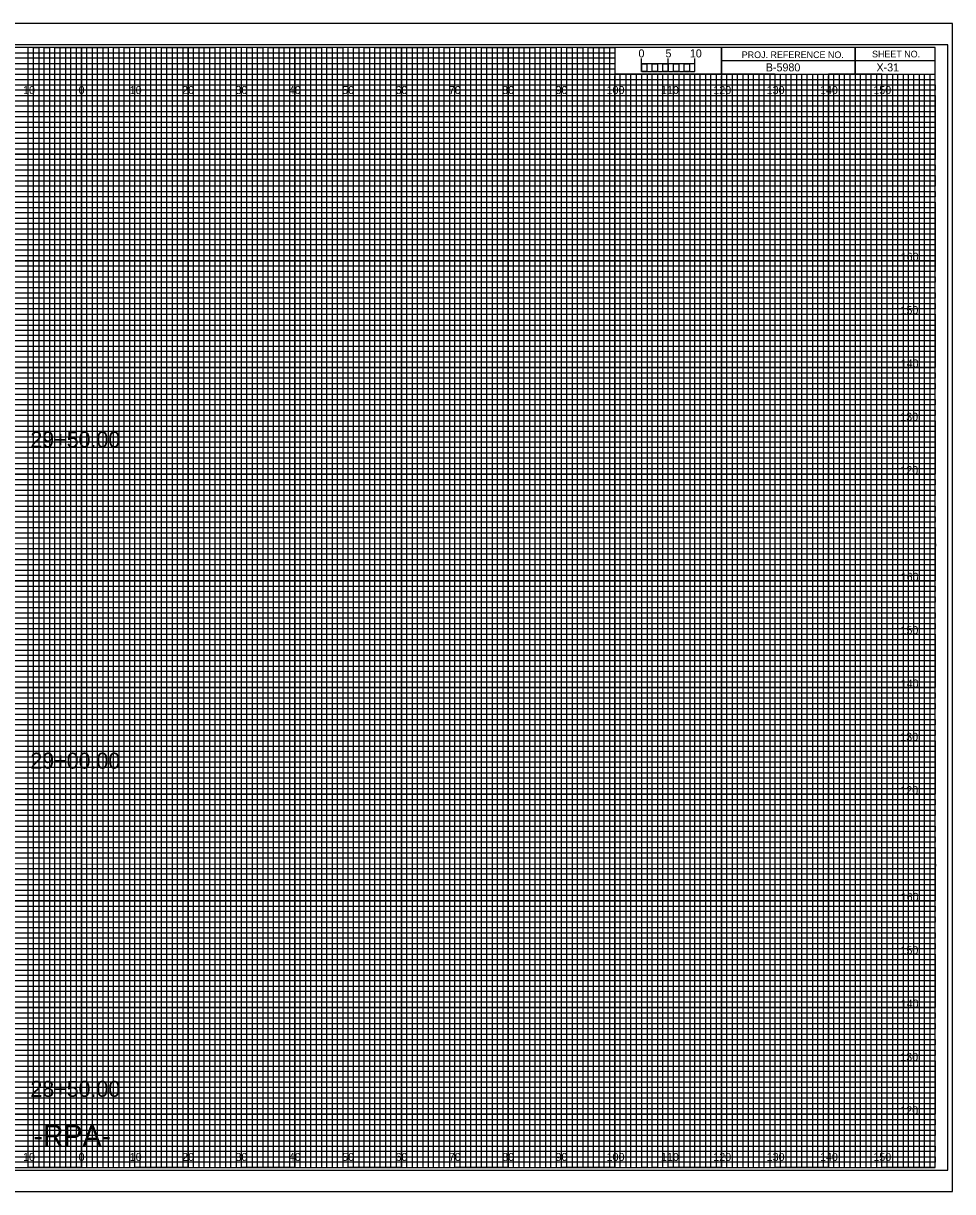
# Model space of a CAD drawing. Extents: x -13 to 323, y -5 to 1974.
# Drawn here: x 149.1 to 323.3, y 1535.5 to 1754.5 of the extents above; entities that cross this region are included whole.
import ezdxf

# ---------------------------------------------------------------- set-up
doc = ezdxf.new("R2010")
doc.units = 0
for name, color, linetype in [('Exist Cross Section Cell', 7, 'Continuous'), ('Exist XS Center Line Elevation Label', 7, 'Continuous'), ('Exist XS Ground Line', 7, 'Continuous'), ('Prop CMT Bridge Girder Bottom Critical Point Inside', 7, 'Continuous'), ('Prop CMT Guardrail Graphics', 7, 'Continuous'), ('Prop CMT Guardrail Widen Shoulder', 7, 'Continuous'), ('Prop CMT Pvmt Course 1', 7, 'Continuous'), ('Prop CMT Pvmt Course 2', 7, 'Continuous'), ('Prop CMT Pvmt Course 3', 7, 'Continuous'), ('Prop CMT Pvmt Surface', 7, 'Continuous'), ('Prop CMT Pvmt Surface Shoulder', 7, 'Continuous'), ('Prop CMT Shld Paved Course 1', 7, 'Continuous'), ('Prop CMT Shld Paved Course 2', 7, 'Continuous'), ('Prop CMT Shld Paved Course 3', 7, 'Continuous'), ('Prop CMT Slope Grass', 7, 'Continuous'), ('Prop CMT Subgrade Earthwork', 7, 'Continuous'), ('Scratch_Level_1', 7, 'Continuous')]:
    doc.layers.add(name, color=color, linetype=linetype)

msp = doc.modelspace()

# ---------------------------------------------------------------- linework, layer by layer
at = {"layer": 'Exist XS Center Line Elevation Label'}
for points in [[(145, 1540), (155, 1540), (155, 1750), (165, 1750), (165, 1540), (175, 1540), (175, 1750), (185, 1750), (185, 1540), (195, 1540), (195, 1750), (205, 1750), (205, 1540), (215, 1540), (215, 1750), (225, 1750), (225, 1540), (235, 1540), (235, 1750), (245, 1750), (245, 1540), (255, 1540), (255, 1750), (259.93, 1750), (260, 1750), (260, 1745), (264.99, 1745), (264.99, 1540), (275, 1540), (275, 1745), (285, 1745), (285, 1540), (295, 1540), (295, 1745), (305, 1745), (305, 1540), (315, 1540), (315, 1745)], [(0, 1745), (275, 1745)], [(0, 1725), (320, 1725), (320, 1735), (0, 1735)], [(0, 1705), (320, 1705), (320, 1715), (0, 1715)], [(0, 1685), (320, 1685), (320, 1695), (0, 1695)], [(0, 1665), (320, 1665), (320, 1675), (0, 1675)], [(0, 1645), (320, 1645), (320, 1655), (0, 1655)], [(0, 1625), (320, 1625), (320, 1635), (0, 1635)], [(0, 1605), (320, 1605), (320, 1615), (0, 1615)], [(0, 1585), (320, 1585), (320, 1595), (0, 1595)], [(0, 1565), (320, 1565), (320, 1575), (0, 1575)], [(0, 1545), (320, 1545), (320, 1555), (0, 1555)]]:
    msp.add_lwpolyline(points, dxfattribs=at)
at = {"layer": 'Exist XS Ground Line'}
for p, q in [((150, 1750), (140, 1750)), ((150, 1540), (150, 1750)), ((170, 1750), (160, 1750)), ((160, 1750), (160, 1540)), ((170, 1540), (170, 1750)), ((190, 1750), (180, 1750)), ((180, 1750), (180, 1540)), ((190, 1540), (190, 1750)), ((210, 1750), (200, 1750)), ((200, 1750), (200, 1540)), ((210, 1540), (210, 1750)), ((230, 1750), (220, 1750)), ((220, 1750), (220, 1540)), ((230, 1540), (230, 1750)), ((250, 1750), (240, 1750)), ((240, 1750), (240, 1540)), ((250, 1540), (250, 1750)), ((260, 1750), (260, 1540)), ((270, 1540), (270, 1745)), ((290, 1745), (280, 1745)), ((280, 1745), (280, 1540)), ((290, 1540), (290, 1745)), ((310, 1745), (300, 1745)), ((300, 1745), (300, 1540)), ((310, 1540), (310, 1745)), ((160, 1540), (150, 1540)), ((180, 1540), (170, 1540)), ((200, 1540), (190, 1540)), ((220, 1540), (210, 1540)), ((240, 1540), (230, 1540)), ((260, 1540), (250, 1540)), ((280, 1540), (270, 1540)), ((300, 1540), (290, 1540)), ((320, 1540), (310, 1540)), ((320, 1540), (320, 1540))]:
    msp.add_line(p, q, dxfattribs=at)
for points in [[(0, 1740), (320, 1740), (320, 1730), (0, 1730)], [(0, 1720), (320, 1720), (320, 1710), (0, 1710)], [(0, 1700), (320, 1700), (320, 1690), (0, 1690)], [(0, 1680), (320, 1680), (320, 1670), (0, 1670)], [(0, 1660), (320, 1660), (320, 1650), (0, 1650)], [(0, 1640), (320, 1640), (320, 1630), (0, 1630)], [(0, 1620), (320, 1620), (320, 1610), (0, 1610)], [(0, 1600), (320, 1600), (320, 1590), (0, 1590)], [(0, 1580), (320, 1580), (320, 1570), (0, 1570)], [(0, 1560), (320, 1560), (320, 1550), (0, 1550)]]:
    msp.add_lwpolyline(points, dxfattribs=at)
at = {"layer": 'Prop CMT Pvmt Course 2'}
for p, q in [((265, 1745.49), (265, 1747.9)), ((265, 1746.9), (265, 1747.9)), ((270, 1745.49), (270, 1747.9)), ((275, 1745.49), (275, 1747.9)), ((275, 1746.9), (275, 1747.9))]:
    msp.add_line(p, q, dxfattribs=at)
for points in [[(275, 1746.9), (265, 1746.9), (265, 1745.49), (275, 1745.49)], [(265, 1746.9), (266, 1746.9), (266, 1745.49), (265, 1745.49)], [(267, 1746.9), (268, 1746.9), (268, 1745.49), (267, 1745.49)], [(269, 1746.9), (270, 1746.9), (270, 1745.49), (269, 1745.49)], [(271, 1746.9), (272, 1746.9), (272, 1745.49), (271, 1745.49)], [(273, 1746.9), (274, 1746.9), (274, 1745.49), (273, 1745.49)]]:
    msp.add_lwpolyline(points, close=True, dxfattribs=at)
at = {"layer": 'Prop CMT Pvmt Course 3'}
msp.add_lwpolyline([(-13.4, 1535.5), (323.3, 1535.5), (323.3, 1754.5), (-13.4, 1754.5)], close=True, dxfattribs=at)
at = {"layer": 'Prop CMT Pvmt Surface'}
for p, q in [((150, 1540), (150, 1750)), ((160, 1540), (160, 1750)), ((170, 1540), (170, 1750)), ((180, 1540), (180, 1750)), ((190, 1540), (190, 1750)), ((200, 1540), (200, 1750)), ((210, 1540), (210, 1750)), ((220, 1540), (220, 1750)), ((230, 1540), (230, 1750)), ((240, 1540), (240, 1750)), ((250, 1540), (250, 1750)), ((260, 1540), (260, 1744.69)), ((270, 1540), (270, 1744.69)), ((280, 1540), (280, 1744.69)), ((290, 1540), (290, 1744.69)), ((300, 1540), (300, 1744.69)), ((310, 1540), (310, 1744.69)), ((0, 1740), (320, 1740)), ((0, 1730), (320, 1730)), ((0, 1720), (320, 1720)), ((0, 1710), (320, 1710)), ((0, 1700), (320, 1700)), ((0, 1690), (320, 1690)), ((0, 1680), (320, 1680)), ((0, 1670), (320, 1670)), ((0, 1660), (320, 1660)), ((0, 1650), (320, 1650)), ((0, 1640), (320, 1640)), ((0, 1630), (320, 1630)), ((0, 1620), (320, 1620)), ((0, 1610), (320, 1610)), ((0, 1600), (320, 1600)), ((0, 1590), (320, 1590)), ((0, 1580), (320, 1580)), ((0, 1570), (320, 1570)), ((0, 1560), (320, 1560)), ((0, 1550), (320, 1550))]:
    msp.add_line(p, q, dxfattribs=at)
at = {"layer": 'Prop CMT Pvmt Surface Shoulder'}
for p, q in [((323.3, 1754.5), (-13.4, 1754.5)), ((-13.4, 1535.5), (323.3, 1535.5))]:
    msp.add_line(p, q, dxfattribs=at)
at = {"layer": 'Prop CMT Shld Paved Course 1'}
for p, q in [((0, 1749), (260, 1749)), ((260, 1747.98), (0, 1747.98)), ((260, 1749), (260, 1747.98)), ((0, 1747), (260, 1747)), ((260, 1745.89), (0, 1745.89)), ((260, 1747), (260, 1745.89)), ((0, 1744), (320, 1744))]:
    msp.add_line(p, q, dxfattribs=at)
for points in [[(0, 1743), (270, 1743), (320, 1743), (320, 1742), (0, 1742)], [(0, 1741), (320, 1741), (320, 1739), (0, 1739)], [(0, 1738), (320, 1738), (320, 1737), (0, 1736.98)], [(0, 1736), (320, 1736), (320, 1734), (0, 1734)], [(0, 1733), (320, 1733), (320, 1732), (0, 1732)], [(0, 1731), (320, 1731), (320, 1729), (0, 1729)], [(0, 1728), (320, 1728), (320, 1727), (0, 1727)], [(0, 1726), (320, 1726), (320, 1724), (0, 1724)], [(0, 1723), (320, 1723), (320, 1722), (0, 1722)], [(0, 1721), (320, 1721), (320, 1719), (0, 1719)], [(0, 1718), (320, 1718), (320, 1717), (0, 1717)], [(0, 1716), (320, 1716), (320, 1713.95), (320, 1713), (320, 1712), (0, 1712)], [(0, 1714), (320, 1714), (320, 1713), (0, 1713)], [(0, 1711), (320, 1711), (320, 1709), (0, 1709.03)], [(0, 1709.03), (320, 1709), (320, 1708), (0, 1708)], [(0, 1707), (320, 1707), (320, 1706), (0, 1706)], [(0, 1704), (320, 1704), (320, 1703), (0, 1703)], [(0, 1702), (320, 1702), (320, 1701), (0, 1701)], [(-0.07, 1698.89), (320, 1698.89), (320, 1697.88), (-0.07, 1697.88)], [(0, 1697), (320, 1697), (320, 1696), (0, 1696)], [(0, 1694), (320, 1694), (320, 1693), (0, 1693)], [(0, 1692), (320, 1692), (320, 1691), (0, 1691)], [(0, 1689), (320, 1689), (320, 1688), (0, 1688)], [(0, 1687), (320, 1687), (320, 1686), (0, 1686)], [(0, 1684), (320, 1684), (320, 1683), (0, 1683)], [(0, 1682), (320, 1682), (320, 1681), (0, 1681)], [(0, 1679), (320, 1679), (319.99, 1677.98), (0, 1678)], [(0, 1677), (320, 1677), (320, 1676), (0, 1676)], [(0, 1674), (320, 1674), (320, 1673), (0, 1673)], [(0, 1672), (320, 1672), (320, 1671), (0, 1671)], [(0, 1669), (320, 1669), (320, 1668), (0, 1668)], [(0, 1667), (320, 1667), (320, 1666), (0, 1666)], [(0, 1664), (320, 1664), (320, 1663), (0, 1663)], [(0, 1662), (320, 1662), (320, 1661), (0, 1661)], [(0, 1659), (320, 1659), (320, 1658), (0, 1658)], [(0, 1656.99), (320.07, 1656.91), (320, 1656), (0, 1656)], [(0, 1654), (320, 1654), (320, 1653), (0, 1653)], [(0, 1652), (320, 1652), (320, 1651), (0, 1651)], [(0, 1649), (320, 1649), (320, 1648), (0, 1648)], [(0, 1647), (320, 1647), (320, 1646), (0, 1646)], [(0, 1644), (320, 1644), (320, 1643), (0, 1643)], [(0, 1642), (320, 1642), (320, 1641), (0, 1641)], [(0, 1639), (320, 1639), (320, 1638), (0, 1638)], [(0, 1637), (320, 1637), (320, 1636), (0, 1636)], [(0, 1634), (320, 1634), (320, 1633), (0, 1633)], [(0, 1632), (320, 1632), (320, 1631), (0, 1631)], [(0, 1629), (320, 1629), (320, 1628), (0, 1628)], [(0, 1627), (320, 1627), (320, 1626), (0, 1626)], [(0, 1624), (320, 1624), (320, 1623), (0, 1623)], [(0, 1622), (320, 1622), (320, 1621), (0, 1621)], [(0, 1619), (320, 1619), (319.99, 1617.98), (0, 1618)], [(0, 1617), (320, 1617), (320, 1616), (0, 1616)], [(0, 1614), (320, 1614), (320, 1613), (0, 1613)], [(0, 1612), (320, 1612), (320, 1611), (0, 1611)], [(0, 1609), (320, 1609), (320, 1608), (0, 1608)], [(0, 1607), (320, 1607), (320, 1606), (0, 1606)], [(0, 1604), (320, 1604), (320, 1603), (0, 1603)], [(0, 1602), (320, 1602), (320, 1601), (0, 1601)], [(0, 1599), (320, 1599), (320, 1598), (0, 1598)], [(0, 1596.99), (320.07, 1596.91), (320, 1596), (0, 1596)], [(0, 1594), (320, 1594), (320, 1593), (0, 1593)], [(0, 1592), (320, 1592), (320, 1591), (0, 1591)], [(0, 1589), (320, 1589), (320, 1588), (0, 1588)], [(0, 1587), (320, 1587), (320, 1586), (0, 1586)], [(0, 1584), (320, 1584), (320, 1583), (0, 1583)], [(0, 1582), (320, 1582), (320, 1581), (0, 1581)], [(0, 1579), (320, 1579), (320, 1578), (0, 1578)], [(0, 1577), (320, 1577), (320, 1576), (0, 1576)], [(0, 1574), (320, 1574), (320, 1573), (0, 1573)], [(0, 1572), (320, 1572), (320, 1571), (0, 1571)], [(0, 1569), (320, 1569), (320, 1568), (0, 1568)], [(0, 1567), (320, 1567), (320, 1566), (0, 1566)], [(0, 1564), (320, 1564), (320, 1563), (0, 1563)], [(0, 1562), (320, 1562), (320, 1561), (0, 1561)], [(0, 1559), (320, 1559), (320, 1558), (0, 1558)], [(0, 1557), (320, 1557), (320, 1556), (0, 1556)], [(0, 1554), (320, 1554), (320, 1553), (0, 1553)], [(0, 1552), (320, 1552), (320, 1551), (0, 1551)], [(0, 1549), (320, 1549), (320, 1548), (0, 1548)], [(0, 1547), (320, 1547), (320, 1546), (0, 1546)], [(0, 1544), (320, 1544), (320, 1543), (0, 1543)], [(0, 1542), (320, 1542), (320, 1541), (0, 1541)]]:
    msp.add_lwpolyline(points, dxfattribs=at)
at = {"layer": 'Prop CMT Shld Paved Course 2'}
for p, q in [((305, 1750), (305, 1745)), ((305, 1745), (305, 1750)), ((280, 1747.5), (280, 1745)), ((320, 1747.49), (280, 1747.49)), ((280, 1745), (320, 1745))]:
    msp.add_line(p, q, dxfattribs=at)
for points in [[(320, 1750), (0, 1750), (0, 1540), (320, 1540)], [(280, 1750), (260, 1750), (260, 1745.03), (280, 1745.03)], [(320, 1750), (280, 1750), (280, 1745), (320, 1745)]]:
    msp.add_lwpolyline(points, close=True, dxfattribs=at)
at = {"layer": 'Prop CMT Shld Paved Course 3'}
for p, q in [((267, 1745), (266.01, 1745)), ((266.01, 1745), (266.01, 1540)), ((267, 1540), (267, 1745)), ((269, 1745), (268, 1745)), ((268, 1745), (268, 1540)), ((269, 1540), (269, 1745)), ((266.01, 1540), (265, 1540)), ((268, 1540), (267, 1540))]:
    msp.add_line(p, q, dxfattribs=at)
for points in [[(150, 1540), (151, 1540), (151, 1750), (152, 1750), (152, 1540)], [(152, 1540), (153, 1540), (153, 1750), (154, 1750), (154, 1540)], [(155, 1540), (156, 1540), (156, 1750), (157, 1750), (157, 1540)], [(157, 1540), (158, 1540), (158, 1750), (159, 1750), (159, 1540)], [(160, 1540), (161, 1540), (161, 1750), (162, 1750), (162, 1540)], [(162, 1540), (163, 1540), (163, 1750), (164, 1750), (164, 1540)], [(165, 1540), (166, 1540), (166, 1750), (167, 1750), (167, 1540)], [(167, 1540), (168, 1540), (168, 1750), (169, 1750), (169, 1540)], [(170, 1540), (171, 1540), (171, 1750), (172, 1750), (172, 1540)], [(172, 1540), (173, 1540), (173, 1750), (174, 1750), (174, 1540)], [(175, 1540), (176, 1540), (176, 1750), (177, 1750), (177, 1540)], [(177, 1540), (178, 1540), (178, 1750), (179, 1750), (179, 1540)], [(180, 1540), (181, 1540), (181, 1750), (182, 1750), (182, 1540)], [(182, 1540), (183, 1540), (183, 1750), (184, 1750), (184, 1540)], [(185, 1540), (186, 1540), (186, 1750), (187, 1750), (187, 1540)], [(187, 1540), (188, 1540), (188, 1750), (189, 1750), (189, 1540)], [(190, 1540), (191, 1540), (191, 1750), (192, 1750), (192, 1540)], [(192, 1540), (193, 1540), (193, 1750), (194, 1750), (194, 1540)], [(195, 1540), (196, 1540), (196, 1750), (197, 1750), (197, 1540)], [(197, 1540), (198, 1540), (198, 1750), (199, 1750), (199, 1540)], [(200, 1540), (201, 1540), (201, 1750), (202, 1750), (202, 1540)], [(202, 1540), (203, 1540), (203, 1750), (204, 1750), (204, 1540)], [(205, 1540), (206, 1540), (206, 1750), (207, 1750), (207, 1540)], [(207, 1540), (208, 1540), (208, 1750), (209, 1750), (209, 1540)], [(210, 1540), (211, 1540), (211, 1750), (212, 1750), (212, 1540)], [(212, 1540), (213, 1540), (213, 1750), (214, 1750), (214, 1540)], [(215, 1540), (216, 1540), (216, 1750), (217, 1750), (217, 1540)], [(217, 1540), (218, 1540), (218, 1750), (219, 1750), (219, 1540)], [(220, 1540), (221, 1540), (221, 1750), (222, 1750), (222, 1540)], [(222, 1540), (223, 1540), (223, 1750), (224, 1750), (224, 1540)], [(225, 1540), (226, 1540), (226, 1750), (227, 1750), (227, 1540)], [(227, 1540), (228, 1540), (228, 1750), (229, 1750), (229, 1540)], [(230, 1540), (231, 1540), (231, 1750), (232, 1750), (232, 1540)], [(232, 1540), (233, 1540), (233, 1750), (234, 1750), (234, 1540)], [(235, 1540), (236, 1540), (236, 1750), (237, 1750), (237, 1540)], [(237, 1540), (238, 1540), (238, 1750), (239, 1750), (239, 1540)], [(240, 1540), (241, 1540), (241, 1750), (242, 1750), (242, 1540)], [(242, 1540), (243, 1540), (243, 1750), (244, 1750), (244, 1540)], [(245, 1540), (246, 1540), (246, 1750), (247, 1750), (247, 1540)], [(247, 1540), (248, 1540), (248, 1750), (249, 1750), (249, 1540)], [(250, 1540), (251, 1540), (251, 1750), (252, 1750), (252, 1540)], [(252, 1540), (253, 1540), (253, 1750), (254, 1750), (254, 1540)], [(255, 1540), (256, 1540), (256, 1750), (257, 1750), (257, 1540)], [(257, 1540), (258, 1540), (258, 1750), (259, 1750), (259, 1540)], [(260, 1540), (261, 1540), (261, 1745), (262.02, 1745), (262.02, 1540)], [(262, 1540), (263, 1540), (263, 1745), (263.99, 1745), (263.99, 1540)], [(270, 1540), (270.98, 1540), (270.98, 1745), (272, 1745), (272, 1540)], [(272, 1540), (273, 1540), (273, 1745), (274.05, 1745), (274.05, 1540)], [(275, 1540), (276, 1540), (276, 1745), (277, 1745), (277, 1540)], [(277, 1540), (278, 1540), (278, 1745), (279, 1745), (279, 1540)], [(280, 1540), (281, 1540), (281, 1745), (282, 1745), (282, 1540)], [(282, 1540), (283, 1540), (283, 1745), (284, 1745), (284, 1540)], [(285, 1540), (286, 1540), (286, 1745), (287, 1745), (287, 1540)], [(287, 1540), (288, 1540), (288, 1745), (289, 1745), (289, 1540)], [(290, 1540), (291, 1540), (291, 1745), (292, 1745), (292, 1540)], [(292, 1540), (293, 1540), (293, 1745), (294, 1745), (294, 1540)], [(295, 1540), (296, 1540), (296, 1745), (297, 1745), (297, 1540)], [(297, 1540), (298, 1540), (298, 1745), (299, 1745), (299, 1540)], [(300, 1540), (301, 1540), (301, 1745), (302, 1745), (302, 1540)], [(302, 1540), (303, 1540), (303, 1745), (304, 1745), (304, 1540)], [(305, 1540), (306, 1540), (306, 1745), (307, 1745), (307, 1540)], [(307, 1540), (308, 1540), (308, 1745), (309, 1745), (309, 1540)], [(310, 1540), (311, 1540), (311, 1745), (312, 1745), (312, 1540)], [(312, 1540), (313, 1540), (313, 1745), (314, 1745), (314, 1540)], [(315, 1540), (316, 1540), (316, 1745), (317, 1745), (317, 1540)], [(317, 1540), (318, 1540), (318, 1745), (319, 1745), (319, 1540)]]:
    msp.add_lwpolyline(points, dxfattribs=at)
at = {"layer": 'Prop CMT Subgrade Earthwork'}
msp.add_lwpolyline([(-10.8, 1539.5), (322.4, 1539.5), (322.4, 1750.5), (-10.8, 1750.5)], close=True, dxfattribs=at)

# ---------------------------------------------------------------- texts
at = {"layer": 'Exist Cross Section Cell'}
for s, p in [('10', (149.04, 1741.25)), ('0', (159.45, 1741.25)), ('0', (159.45, 1741.25)), ('10', (169.04, 1741.25)), ('20', (178.86, 1741.25)), ('30', (188.86, 1741.25)), ('40', (198.86, 1741.25)), ('50', (208.86, 1741.25)), ('60', (218.86, 1741.25)), ('70', (228.86, 1741.25)), ('80', (238.86, 1741.25)), ('90', (248.86, 1741.25)), ('100', (258.44, 1741.25)), ('110', (268.62, 1741.25)), ('120', (278.44, 1741.25)), ('130', (288.44, 1741.25)), ('140', (298.44, 1741.25)), ('150', (308.44, 1741.25)), ('10', (149.04, 1541.25)), ('0', (159.45, 1541.25)), ('0', (159.45, 1541.25)), ('10', (169.04, 1541.25)), ('20', (178.86, 1541.25)), ('30', (188.86, 1541.25)), ('40', (198.86, 1541.25)), ('50', (208.86, 1541.25)), ('60', (218.86, 1541.25)), ('70', (228.86, 1541.25)), ('80', (238.86, 1541.25)), ('90', (248.86, 1541.25)), ('100', (258.44, 1541.25)), ('110', (268.62, 1541.25)), ('120', (278.44, 1541.25)), ('130', (288.44, 1541.25)), ('140', (298.44, 1541.25)), ('150', (308.44, 1541.25))]:
    msp.add_text(s, height=1.5, dxfattribs=at).set_placement(p)
at = {"layer": 'Prop CMT Bridge Girder Bottom Critical Point Inside'}
for s, p in [('5', (269.47, 1748.12)), ('10', (274.04, 1748.12))]:
    msp.add_text(s, height=1.5, dxfattribs=at).set_placement(p)
at = {"layer": 'Prop CMT Guardrail Graphics'}
msp.add_text('B-5980', height=1.5, dxfattribs=at).set_placement((288.28, 1745.5))
at = {"layer": 'Prop CMT Guardrail Widen Shoulder'}
msp.add_text('X-31', height=1.5, dxfattribs=at).set_placement((309.02, 1745.5))
at = {"layer": 'Prop CMT Pvmt Course 1'}
for s, p in [('160', (313.57, 1710)), ('150', (313.52, 1700)), ('140', (313.57, 1690)), ('130', (313.49, 1680)), ('120', (313.5, 1670)), ('160', (313.57, 1650)), ('150', (313.52, 1640)), ('140', (313.57, 1630)), ('130', (313.49, 1620)), ('120', (313.5, 1610)), ('160', (313.57, 1590)), ('150', (313.52, 1580)), ('140', (313.57, 1570)), ('130', (313.49, 1560)), ('120', (313.5, 1550))]:
    msp.add_text(s, height=1.5, dxfattribs=at).set_placement(p)
at = {"layer": 'Prop CMT Pvmt Course 2'}
msp.add_text('0', height=1.5, dxfattribs=at).set_placement((264.41, 1748.12))
at = {"layer": 'Prop CMT Shld Paved Course 2'}
for s, p in [('PROJ. REFERENCE NO.', (283.77, 1747.99)), ('SHEET NO.', (308.19, 1748.12))]:
    msp.add_text(s, height=1.25, dxfattribs=at).set_placement(p)
at = {"layer": 'Prop CMT Slope Grass'}
for s, p in [('29+50.00', (150.41, 1675)), ('29+00.00', (150.41, 1614.79)), ('28+50.00', (150.41, 1553.27))]:
    msp.add_text(s, height=3, dxfattribs=at).set_placement(p)
at = {"layer": 'Scratch_Level_1'}
msp.add_text('-RPA-', height=4, dxfattribs=at).set_placement((150.97, 1544))

doc.saveas('drawing.dxf')
